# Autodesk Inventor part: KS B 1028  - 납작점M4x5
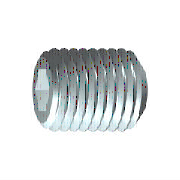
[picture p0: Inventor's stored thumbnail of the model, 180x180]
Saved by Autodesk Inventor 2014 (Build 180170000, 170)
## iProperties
IsCustomPart: 0
Created: 2009-02
Part Number: KS B 1028  - 납작점M4x5
Material: 강철, 연강
Description: 6각 소켓 머리 없는 멈춤 나사
Document SubType Name: Modeling
Standard: KS B 1028
Designer: KYOUNG IL JANG
Standards Organization: KS
Language: ko-KR
Size Designation: 납작점M4x5
Categories: <MemberInstance><Categories><Category DisplayName="조임쇠" InternalName="e4da775c-781d-43d5-af7c-5136215cf5a6" Mnemonic="FSTN"><Category DisplayName="볼트" InternalN
Density: 7.86 g/cm^3
Appearance: 강철
Mass: 0.401763 g
Surface Area: 0.994256 cm^2
Volume: 0.0511149 cm^3
Author: KYOUNG IL JANG
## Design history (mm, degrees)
sketch "스케치1"
  geometry: L1 (0, 0)-(1.833, 0); L2 (5, 1.155)-(5, 2); L3 (5, 2)-(0, 2); L4 (5, 1.155)-(2.5, 1.155); L5 (2.5, 1.155)-(1.833, 0); L6 (0, -0.4)-(0, 2.4) reference; L7 (0, 2)-(0, 0)
  constraints: 13 end point, 3 parallel, 1 collinear, 1 perpendicular, 1 point on line
  dimensions: "d0" = 2.5 distance of L2.start L4.end (= INTI); "d1" = 60 deg angle of L5 L1; "d2" = 4 diameter of L3 L1 (= NND); "d3" = 2.3094 diameter of L4 L1 (= 1.1547 x SW); "d5" = 5 distance from line of L2 L3.end (= NLG)
revolve "본체" sketch "스케치1" stored, may be unused: angle "d6" = 90 deg
sketch "스케치2"
  geometry: L1 (-0.577, 1)-(0.577, 1); L2 (0.577, 1)-(1.155, 0); L3 (1.155, 0)-(0.577, -1); L4 (0.577, -1)-(-0.577, -1); L5 (-0.577, -1)-(-1.155, 0); L6 (-1.155, 0)-(-0.577, 1); A1 r 1.155 centre (0, 0) between (-0.577, 1) and (0.577, 1) reference; 2 further points
  constraints: 12 end point, 2 point on circle, 1 coincident, 1 horizontal, 11 other
extrude "슬롯" join sketch "스케치2" taper "d9" = 0 deg; stored distance "d21" = 10
workaxis "Work Axis1"
workplane "Work Plane1"
body "Solid1"
chamfer "모따기1" distance "d7" = 0.42941 (= -0.5 x GD1 + 0.5 x NND); stored, may be unused: angle "d8" = 45 deg (= FAWI), second distance "d29" = 0.42941 (= -0.5 x GD1 + 0.5 x NND)
feature "스레드" dims "d11" = 5 (= NLG), "d12" = 0
chamfer "모따기2" distance "d13" = 0.42941 (= -0.5 x GD1 + 0.5 x NND); stored, may be unused: angle "d14" = 45 deg (= FAWI), second distance "d30" = 0.42941 (= -0.5 x GD1 + 0.5 x NND)
other parameters: "NND" = 4 [user parameter; used in 5 equation terms], "NLG" = 5 [user parameter; used in 2 equation terms], "INTI" = 2.5 [user parameter; used in 1 equation term], "FAWI" = 45 deg [user parameter; used in 2 equation terms], "SW" = 2 [user parameter; used in 2 equation terms], "GD1" = 3.14117 (= THREADDIA - 1.2269 x PTC) [user parameter; used in 4 equation terms], "d4" = 0, "FAWI1" = 45 deg [user parameter], "d15" = 0, "d31" = 0, "GUL" = 0.42941 (= 0.61345 x PTC) [user parameter], "SPD" = 2.5 [user parameter], "TPU" = 14.28571 (computed from PTC) [user parameter], "TOA" = 30 deg [user parameter], "THREADDIA" = 4 [user parameter; used in 1 equation term], "PTC" = 0.7 [user parameter; used in 4 equation terms], "GAL" = 0.42941 (= 0.61345 x PTC) [user parameter], "E0" = 2.31 (= 1.155 x SW) [user parameter]
